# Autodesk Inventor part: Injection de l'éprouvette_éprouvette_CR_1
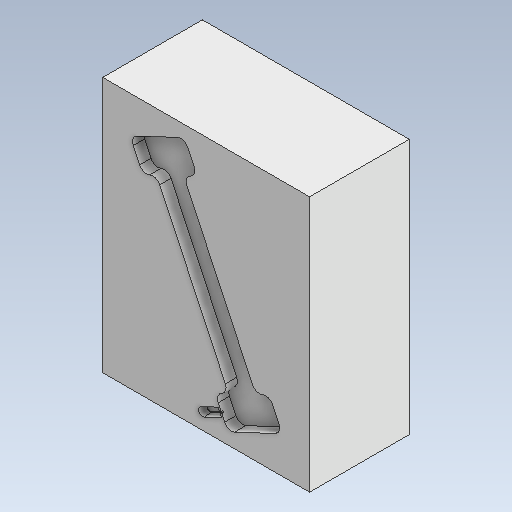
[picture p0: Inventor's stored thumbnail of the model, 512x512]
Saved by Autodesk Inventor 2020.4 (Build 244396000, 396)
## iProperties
Created: 2021-10
Part Number: Injection de l'éprouvette_éprouvette_CR_1
Material: Générique
Document SubType Name: Modeling
Designer: mel
Density: 1 g/cm^3
Appearance: Par défaut
Author: mel
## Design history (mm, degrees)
feature "Sculpter1"
node "Injection de l'éprouvette_éprouvette_CR_Base"
feature "Sculpter2"
feature "Solide2::Injection de l'éprouvette_éprouvette_CR_Base"
tag "FonctionRepérage2"
node "Solide1"
feature "Surface1"
body "Srf1"
node "Solide2"
feature "Injection de l'éprouvette_éprouvette_CR_Base_Corps"
feature "Surface2"
body "Srf2"
